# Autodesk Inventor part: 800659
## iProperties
Created: 2007-11
Part Number: 800659
Document SubType Name: Modeling
Designer: TH
Density: 8.08 g/cm^3
Mass: 32.4694 g
Surface Area: 19.7101 cm^2
Volume: 4.01849 cm^3
Material: Stainless Steel
Description: H343 BOLT M12 X 20
Component Category: Fasteners
Author: TH
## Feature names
1. Extrusion1
2. Revolution1
3. Revolution2
4. Fillet1
